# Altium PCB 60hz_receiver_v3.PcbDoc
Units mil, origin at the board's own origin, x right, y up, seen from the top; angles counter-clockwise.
Board outline 2650 x 1300 mil, 2 copper layers (Top Layer, Bottom Layer); 64 components, 31 nets, 144 pads, 25 vias.
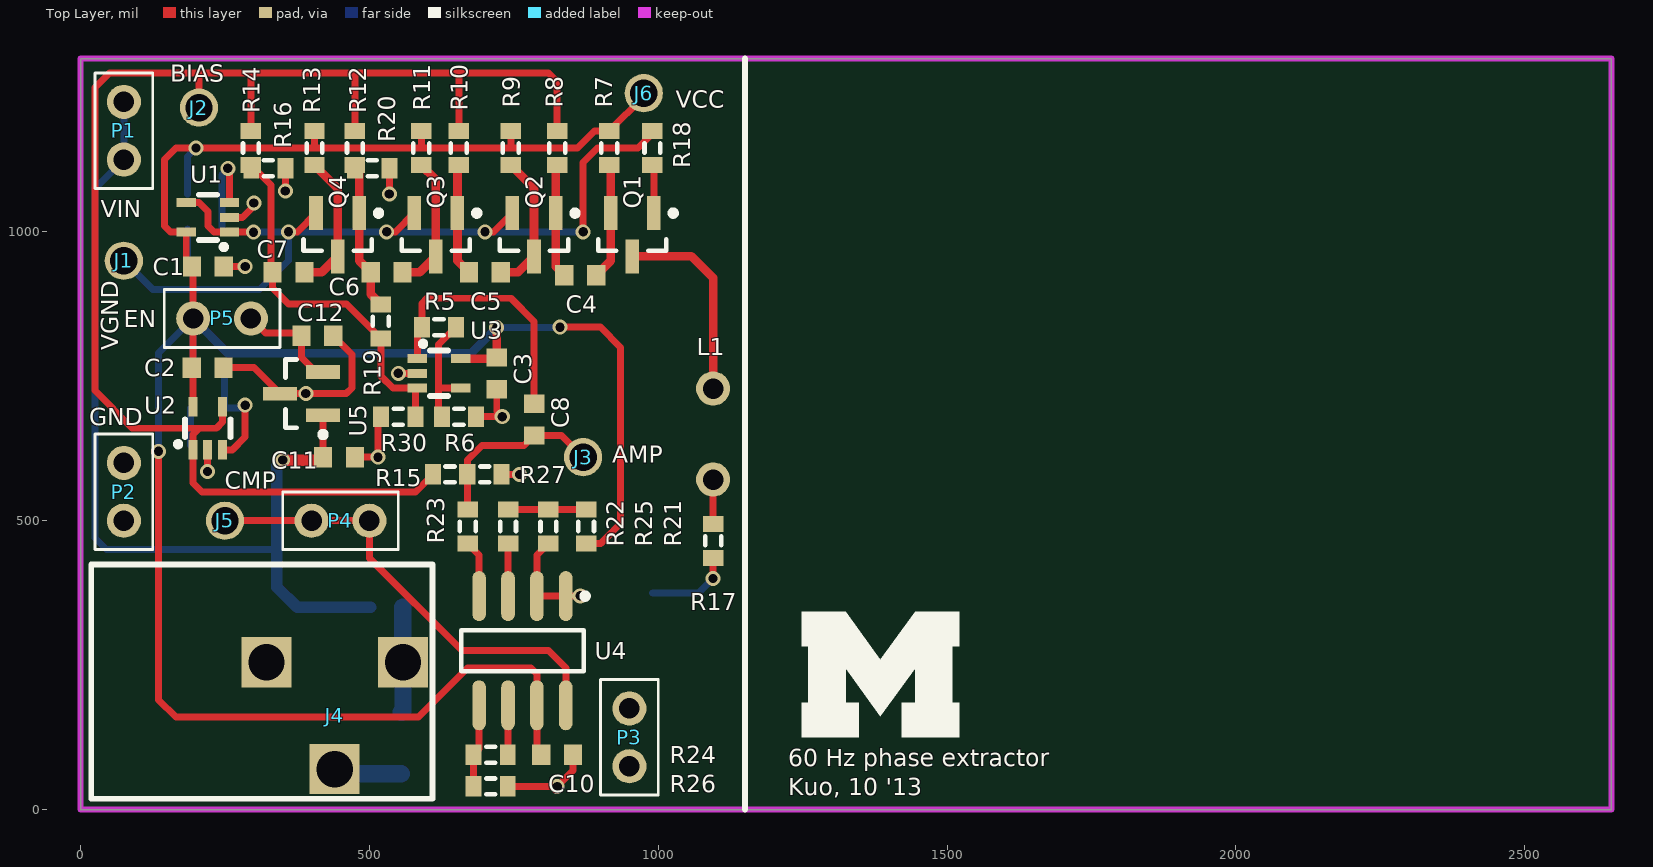
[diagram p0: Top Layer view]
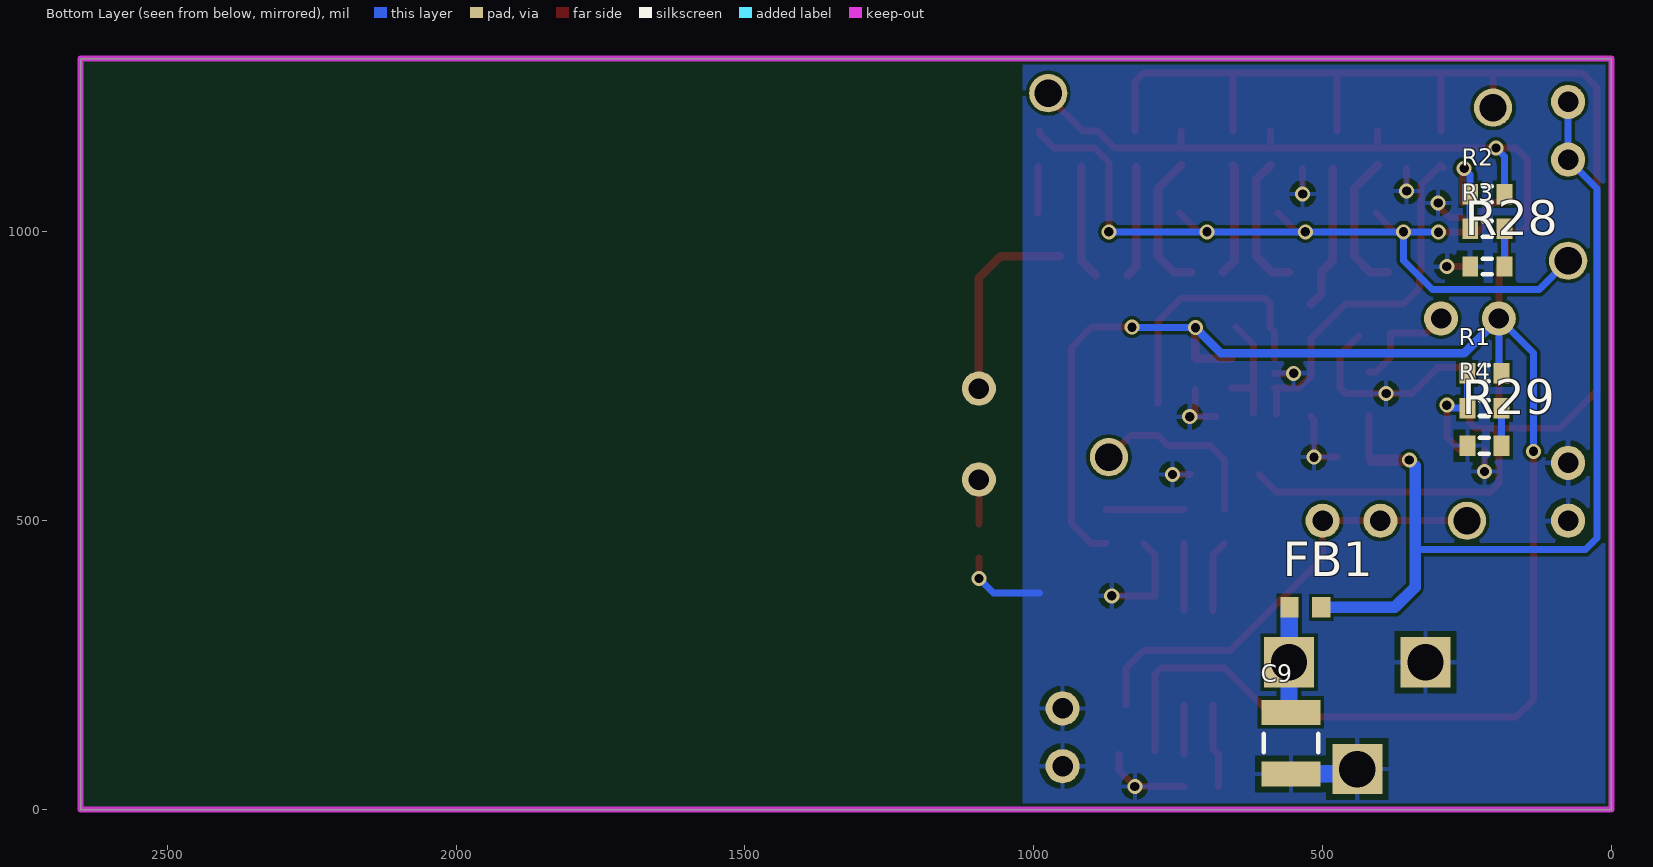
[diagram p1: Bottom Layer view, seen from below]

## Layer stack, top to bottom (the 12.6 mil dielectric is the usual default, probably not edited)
Top Layer: signal copper 1.4
Dielectric: dielectric 12.6, FR-4, Dk 4.8
Bottom Layer: signal copper 1.4

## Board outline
0,0 2650,0 2650,1300 0,1300

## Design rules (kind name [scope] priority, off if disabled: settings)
Clearance "Clearance~Sunstone Circuits" [All] p1: gap=6 // Sunstone Circuits Minimum Clearance Rule (MLB~4&6 Layer Designs)
HoleSize "HoleSize~Sunstone Circuits" [All] p1: absolutevalues=TRUE maxlimit=251 minlimit=8 maxpercent=80.000 minpercent=20.000 // Sunstone Circuits Hole Size Rule (MLB~4&6 Layer Designs)
HoleSize Testpoint [All] p2: absolutevalues=TRUE maxlimit=100 minlimit=1 maxpercent=80.000 minpercent=20.000
HoleSize TestPointUsage [All] p3: absolutevalues=TRUE maxlimit=100 minlimit=1 maxpercent=80.000 minpercent=20.000
MinimumAnnularRing "MinimumAnnularRing~Sunstone Circuits" [All] p1: minimumring=7 // Sunstone Circuits Minimum Annular Ring (MLB~4&6 Layer Designs)
PlaneClearance "PlaneClearance~Sunstone Circuits" [All] p1: clearance=12 // Sunstone Circuits Power Plane Clearance Rule (MLB~4&6 Layer Designs)
PlaneConnect "PlaneConnect~Sunstone Circuits" [All] p1: planeconnectstyle=Relief reliefexpansion=10 reliefentries=4 reliefconductorwidth=8 reliefairgap=10 // Sunstone Circuits Power Plane Connect Rule (MLB~4&6 Layer Designs)
PolygonConnect "PolygonConnect~Sunstone Circuits" [All] p1: connectstyle=Relief reliefconductorwidth=8 reliefentries=4 polygonreliefangle="90 Angle" airgapwidth=10 // Sunstone Circuits Polygon Connect Style (MLB~4&6 Layer Designs)
RoomDefinition 60hz_receiver_v3 [InComponentClass('60hz_receiver_v3')] p1: confinementstyle=ConfineIn formatcopy=TRUE lockcomponents=FALSE outline 1.35,3.78 1.35,439.29 12.5,439.29 12.5,1287.5 915.4,1287.5 915.4,1294.9 1035,1294.9 1035,1083.74 1045.71,1083.74 1045.71,771.27 1137.53,771.27 1137.53,528.73 1128.62,528.73 1128.62,405.79 1012.5,405.79 1012.5,12.5 769.21,12.5 769.21,6.38 624.29,6.38 624.29,3.78
RoutingVias "RoutingVias~Sunstone Circuits" [All] p1: holewidth=16 width=30 viastyle="Through Hole" minholewidth=8 minwidth=24 maxholewidth=20 maxwidth=40 // Sunstone Circuits Routing Vias Rule (MLB~4&6 Layer Designs)
ShortCircuit "ShortCircuit~Sunstone Circuits" [All] p1: allowed=FALSE // Sunstone Circuits Short Circuit Rule~Do Not Allow (MLB~4&6 Layer Designs)
SolderMaskExpansion "Tent vias" [isVia] p1: expansion=-10 // Tent vias
SolderMaskExpansion "SolderMaskExpansion~Sunstone Circuits" [All] p2: expansion=3 // Sunstone Circuits Solder Mask Expansion Rule (MLB~4&6 Layer Designs)
ViasUnderSMD "ViasUnderSMD~Sunstone Circuits" [All] p1: allowed=FALSE // Sunstone Circuits Vias Under SMD~Do Not Allow (MLB~4&6 Layer Designs)
Width "Width~Sunstone Circuits" [All] p1: maxlimit=100 minlimit=6 preferedwidth=10 // Sunstone Circuits Minimum Width Rule (MLB~4&6 Layer Designs)
24 further rules are at their usual default settings.

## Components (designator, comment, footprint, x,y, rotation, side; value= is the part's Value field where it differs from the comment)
C1 "Cap Semi" 1608[0603] 220.47,940 r180 top
C2 "Cap Semi" 1608[0603] 220,765 r180 top
C3 "Cap Semi" 1608[0603] 720.47,755 r90 top
C4 "Cap Semi" 1608[0603] 865,925 r180 top
C5 "Cap Semi" 1608[0603] 700,930 r180 top
C6 "Cap Semi" 1608[0603] 530,930 r180 top
C7 "Cap Semi" 1608[0603] 360,930 r180 top
C8 "Cap Semi" 1608[0603] 785,675 r270 top
C9 "47uF" C1210 555,115 r90 bottom
C10 "Cap Semi" 1608[0603] 825,95 r180 top
C11 "Cap Semi" 1608[0603] 447.4,610 r180 top
C12 "Cap Semi" 1608[0603] 410,820 r180 top
FB1 "BLM18PG300SN1D" 1608[0603] 530,350 r180 bottom
J1 "5004" TestPoint 75,950 r0 top
J2 "5004" TestPoint 205,1215 r0 top
J3 "5004" TestPoint 870,610 r0 top
J4 "PJ-102AH" PJ-102AH 440,255 r90 top
J5 "5004" TestPoint 250,500 r270 top
J6 "5004" TestPoint 975,1240 r0 top
L1 "Inductor Iron" "charging coil" 1095,650 r90 top
P1 "1 x 2 header" "1x2 header" 75,1175 r90 top
P2 "1 x 2 header" "1x2 header" 75,550 r90 top
P3 "1 x 2 header" "1x2 header" 950,125 r270 top
P4 "1 x 2 header" "1x2 header" 450,500 r180 top
P5 "1 x 2 header" "1x2 header" 245,850 r0 top
Q1 "2SK3557" SOT23-3N 955,995 r270 top
Q2 "Si2312CDS" SOT23-3N 785,995 r270 top
Q3 "Si2312CDS" SOT23-3N 615,995 r270 top
Q4 "Si2312CDS" SOT23-3N 445,995 r270 top
R1 "Res3" J1-0603 220,755 r0 bottom
R2 "Res3" J1-0603 215,1065 r180 bottom
R3 "Res3" J1-0603 215,1005 r0 bottom
R4 "Res3" J1-0603 220,695 r180 bottom
R5 "Res3" J1-0603 620.47,835 r0 top
R6 "Res3" J1-0603 655,680 r0 top
R7 "Res3" J1-0603 915,1145 r90 top
R8 "Res3" J1-0603 825,1145 r270 top
R9 "Res3" J1-0603 745,1145 r90 top
R10 "Res3" J1-0603 655,1145 r270 top
R11 "Res3" J1-0603 590,1145 r90 top
R12 "Res3" J1-0603 475,1145 r270 top
R13 "Res3" J1-0603 405,1145 r90 top
R14 "Res3" J1-0603 295,1145 r270 top
R15 "Res3" J1-0603 639.53,580 r0 top
R16 "Res3" J1-0603 325,1110 r0 top
R17 "Res3" J1-0603 1095,465 r270 top
R18 "Res3" J1-0603 990,1145 r270 top
R19 "Res3" J1-0603 520,845 r90 top
R20 "Res3" J1-0603 505,1110 r0 top
R21 "Res3" J1-0603 875,490 r270 top
R22 "Res3" J1-0603 740,490 r270 top
R23 "Res3" J1-0603 670,490 r270 top
R24 "Res3" J1-0603 710,95 r0 top
R25 "Res3" J1-0603 810,490 r90 top
R26 "Res3" J1-0603 710,40 r180 top
R27 "Res3" J1-0603 699.53,580 r0 top
R28 "Res3" J1-0603 215,940 r0 bottom
R29 "Res3" J1-0603 220,630 r0 bottom
R30 "Res3" J1-0603 550,680 r180 top
U1 "LPV521" SC70-5 220.47,1025 r90 top
U2 "LPV521" SC70-5 220,660 r0 top
U3 "LPV521" SC70-5 620.47,755 r270 top
U4 "LTC1540" SOIC-8 765,275 r270 top
U5 "MAX6010" SOT23-3N 382.4,720 r180 top

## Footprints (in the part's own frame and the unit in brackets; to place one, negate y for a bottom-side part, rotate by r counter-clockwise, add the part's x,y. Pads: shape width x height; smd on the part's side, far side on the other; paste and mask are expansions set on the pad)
"1x2 header" [mm] "1x2 header, 100 mils"
  round 1.5 hole 0.9: 1(-1.27,0) 2(1.27,0)
  silkscreen extent -2.54,-1.27 2.54,1.27, body extent -2.53,-1.26 2.53,1.26, height 8.38
1608[0603] [mm] "Chip Capacitor, Body 1.6x0.8mm, IPC High Density"
  rect 0.8x0.9 smd: 1(-0.7,0) 2(0.7,0)
  body extent -0.87,-0.48 0.87,0.48, height 1.3
C1210 [mm] "Chip Capacitor, Body 3.2x2.5mm, IPC High Density"
  rect 1.1x2.6 smd: 1(-1.35,0) 2(1.35,0)
  silkscreen extent -0.4,-1.2 0.4,1.2, body extent -1.7,-1.35 1.7,1.35, height 1.3
"charging coil" [mm]
  round 1.5 hole 0.9: 1(-2,0) 2(2,0)
J1-0603 [mm] "Chip Resistor, Body 1.6x0.8mm, IPC High Density"
  rect 0.7x0.9 smd: 1(-0.75,0) 2(0.75,0)
  silkscreen extent -0.2,-0.35 0.2,0.35, body extent -0.85,-0.48 0.85,0.48, height 0.9
PJ-102AH [mm] "Power Jack"
  rect 2.2x2.2 hole 1.6: 1(0,-3) 2(0,3) 3(-4.7,0)
  silkscreen extent -6,-4.3 4.3,10.7, body extent -5.75,-3.99 4.08,10.89, height 10
SC70-5 [mm]
  rect 0.4x0.85 smd: 1(-0.65,-0.95) 2(0,-0.95) 3(0.65,-0.95) 4(0.65,0.95) 5(-0.65,0.95)
  silkscreen extent -1.4,-0.8 1,0.4, body extent -0.9,-0.6 0.9,0.6, height 0.8
SOIC-8 [mm] "SOIC, 8-Leads, Body 5.10x3.91mm, Pitch 1.27mm, IPC Medium Density"
  oval 2.2x0.6 smd: 1(-2.4,1.905) 2(-2.4,0.635) 3(-2.4,-0.635) 4(-2.4,-1.905) 5(2.4,-1.905) 6(2.4,-0.635) 7(2.4,0.635) 8(2.4,1.905)
  silkscreen extent -2.52,-2.7 0.9,2.88, body extent -2,-2.7 2,2.7, height 1.75
SOT23-3N [mm] "SOT23, 3-Leads, Body 2.9x1.3mm, Pitch 0.95mm, Lead Span 2.5mm, IPC Medium Density"
  rect 1.5x0.6 smd: 1(-0.95,0.95) 2(-0.95,-0.95) 3(0.95,0)
  silkscreen extent -1.07,-1.5 0.7,1.93, body extent -0.7,-1.5 0.7,1.5, height 1.1
TestPoint [mm]
  round 1.68 hole 1.2: 1(0,0)
  body extent -1.26,-1.27 1.27,1.27, height 4.57

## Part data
C1 C2 C3 C4 C5 C6 C7 C8 C10 C11 C12: "Capacitor (Semiconductor SIM Model)"
C9: library part "Cap Semi", "Capacitor (Semiconductor SIM Model)"
FB1: library part "Ferrite Bead", "FERRITE CHIP 30 OHM 1000MA 0603"
J1 J2 J3 J5 J6: library part TestPoint, "TEST POINT PC MINI .040\"D YELLOW"
J4: "CONN PWR JACK 2.1X5.5MM HIGH CUR"
L1: "Magnetic-Core Inductor"
P1 P2 P3 P4 P5: "100 mils standard header"
Q1: "N-Channel JFET"
Q2 Q3 Q4: "N-Channel 20 V (D-S) MOSFET"
R1 R2 R3 R4 R5 R6 R7 R8 R9 R10 R11 R12 R13 R14 R15 R16 R17 R18 R19 R20 R21 R22 R23 R24 R25 R26 R27 R28 R29 R30: "Resistor"
U1 U2 U3: "Nanopower, 1.8V, RRIO, CMOS Input, Operational Amplifier"
U4: "Nanopower Comparator  with Reference"
U5: "Precision Micropower Shunt Voltage Reference"

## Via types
v1: diameter 26, hole 16, Top Layer to Bottom Layer, 25 vias

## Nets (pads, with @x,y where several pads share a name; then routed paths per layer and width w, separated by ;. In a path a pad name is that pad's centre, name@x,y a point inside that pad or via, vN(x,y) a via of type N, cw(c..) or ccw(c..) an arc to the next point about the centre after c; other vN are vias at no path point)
AMP_OUT: C8.1 R5.1 U3.1 | length 455.4
  Top Layer w12: U3.1 583.07,827.13 R5.1 590.94,875.94 600,885 745,885 785,845 C8.1
AMP_OUT_OFFSET: C8.2 J3.1 R15.2 R23.1 R27.1 | length 318.6
  Top Layer w12: R23.1 670,605 695,630 767.56,630 C8.2 832.56,647.44 J3.1
CMP_REF: R21.1 R22.1 R25.2 | length 135
  Top Layer w12: R22.1 R21.1
GND: C1.1 C2.1 C3.1 C9.1 C10.1 C11.1 C12.1 J4.2 J4.3 P2.1 P2.2 P3.1 P3.2 R6.2 R16.2 R17.2 R20.2 R25.1 R26.1 R27.2 R28.2 R29.2 R30.2 U1.2 U2.2 U3.2 U4.1 U4.2 U5.3 | length 1431.7
  Top Layer w12: v1(220,585) U2.2 ; C2.1 300,765 U5.3 v1(390,720) 460,720 470,730 470,787.56 C12.1 ; C1.1 v1(285,940) ; U1.2 280,1025 300,1045 v1(300,1050) ; v1(354.53,1070.47) R16.2 ; C11.1 v1(515,610) 515,674.53 R30.2 ; v1(534.53,1065.47) R20.2 ; v1@549.82,755.18 v1(550.18,755.18) 550.36,755 U3.2 ; R6.2 v1(730,680) 720.47,689.53 C3.1 ; R27.2 v1(760,580) ; R26.1 v1(825,40) 852.56,67.56 C10.1 ; R25.1 790,440.47 U4.2 U4.1 840.51,370 v1(865,370) ; v1(1095,400) R17.2
  Bottom Layer w12: 990,375 1070,375 v1(1095,400)
  Bottom Layer w30: J4.3 448.11,61.85 C9.1
NetC4_1: C4.1 Q1.2 R7.1 | length 198.2
  Top Layer w15: C4.1 917.6,950.04 Q1.2 R7.1@917.6,1112.87
NetC4_2: C4.2 Q2.1 R8.2 | length 194.1
  Top Layer w15: R8.2@822.4,1112.87 Q2.1 822.4,940.04 C4.2
NetC5_1: C5.1 Q2.3 R9.1 | length 243.3
  Top Layer w15: C5.1 757.4,930 Q2.3 785,1075.47 R9.1
NetC5_2: C5.2 Q3.1 R10.2 | length 194.8
  Top Layer w15: R10.2 652.4,1112.87 Q3.1 652.4,950.04 C5.2
NetC6_1: C6.1 Q3.3 R11.1 | length 237.1
  Top Layer w15: C6.1 587.4,930 Q3.3 615,1090.47 R11.1
NetC6_2: C6.2 Q4.1 R12.2 R19.2 R20.1 | length 249.1
  Top Layer w15: R20.1@482.4,1108.07 Q4.1 482.4,950.04 C6.2 502.44,892.09 R19.2
NetC7_1: C7.1 Q4.3 R13.1 | length 243.3
  Top Layer w15: C7.1 417.4,930 Q4.3 445,1075.47 R13.1
NetC7_2: C7.2 R14.2 R16.1 R19.1 R30.1 U3.3 | length 637.3
  Top Layer w12: R14.2@290.47,1110.94 R14.2 329.53,1080.94 329.53,932.91 C7.2 332.44,902.56 360,875 460.47,875 R19.1 520,750 540.59,729.41 U3.3 ; R30.1@580,684.53 U3.3@580,726.34
NetC9_2: C9.2 FB1.1 J4.1 | length 182.6
  Bottom Layer w30: C9.2 558.11,171.26 J4.1 ; J4.1@557.56,255.55 FB1.1
NetC12_2: C12.2 P5.2 U5.2 | length 188
  Top Layer w12: P5.2 320,825 382.44,825 382.44,782.56 407.6,757.4 U5.2
NetJ5_1: J5.1 P4.1 P4.2 U4.8 | length 798.2
  Top Layer w12: J5.1 P4.2 P4.1 500,435 660,275 810,275 840,245 U4.8
NetL1_1: L1.1 R17.1 | length 76.7
  Top Layer w12: R17.1 L1.1
NetL1_2: L1.2 Q1.3 | length 346.8
  Top Layer w15: Q1.3 1057.4,957.6 1095,920 L1.2
NetQ1_1: Q1.1 R18.2 | length 80.7
  Top Layer w12: Q1.1 R18.2@992.4,1113.07
NetR3_1: R3.1 R28.1 | length 65
  Bottom Layer w12: R28.1 R3.1
NetR4_2: R4.2 R29.1 | length 65
  Bottom Layer w12: R29.1 R4.2
NetR5_2: R5.2 R6.1 U3.4 | length 199.2
  Top Layer w12: R6.1@620,685.47 620,805 R5.2 ; 620.59,729.41 U3.4
NetR22_2: R22.2 U4.3 | length 116
  Top Layer w12: U4.3@740,344.49 R22.2
NetR23_2: R23.2 U4.4 | length 124.3
  Top Layer w12: R23.2 690,440.47 U4.4 U4.4@690,344.49
NetR24_1: R24.1 R26.2 U4.5 | length 144.5
  Top Layer w12: R26.2 R24.1 690,104.53 U4.5
NetR24_2: R24.2 U4.6 | length 85
  Top Layer w12: R24.2@740,95.47 U4.6
REF_GND: R2.1 R3.2 U1.3 | length 155.8
  Top Layer w12: v1(255,1110) 257.87,1107.13 U1.3
  Bottom Layer w12: R3.2 R2.1 244.53,1099.53 ; v1@254.53,1109.53 v1(255,1110)
VBIAS: R1.2 R4.1 U2.3 | length 196.2
  Top Layer w12: U2.3 262.6,622.6 285,645 v1(285,700)
  Bottom Layer w12: R4.1 280,695 v1(285,700) ; R4.1@249.53,700 R1.2
VBIAS_BUFFERED: J2.1 R8.1 R10.1 R12.1 R14.1 R15.1 U2.1 U2.4 | length 2599.6
  Top Layer w12: 89.41,660.59 25,725 25,1250 50,1275 205,1275 ; 90,660 205,660 ; J2.1 205,1275 ; U2.4 245.59,670.59 235,660 205,660 ; R14.1 295,1275 ; R12.1 475,1275 ; R15.1 580,550 210,550 194.41,565.59 U2.1 194.41,649.41 205,660 ; R10.1 655,1275 ; R8.1 825,1260 810,1275 475,1275 ; 205,1275 295,1275 ; 295,1275 475,1275
VCC3: C1.2 C2.2 C3.2 C10.2 J6.1 P5.1 R1.1 R2.2 R7.2 R9.2 R11.2 R13.2 R21.2 U1.5 U2.5 U3.5 U4.7 | length 4416.5
  Top Layer w12: v1(135,620) 135,190 165,160 585,160 670,245 780,245 790,235 U4.7 C10.2@790,102.44 ; C1.2 183.07,949.84 U1.5 155.59,999.41 145,1010 145,1125 165,1145 v1(200,1145) 860,1145 889.53,1174.53 R7.2 975,1234.53 J6.1@975,1235 ; U2.5@195,697.99 P5.1 C1.2@195,937.91 ; 405,1145 R13.2 ; 590,1145 R11.2 ; 745,1145 R9.2 ; v1(830,835) 900,835 935,800 935,495 900.47,460.47 R21.2
  Top Layer w15: U3.5 C3.2@718.5,780.59 ; v1(720,834.06) 720.47,834.53 C3.2
  Bottom Layer w12: v1(135,620) 135,790 P5.1 R1.1@195,759.53 ; R2.2 185.47,1130.47 v1(200,1145) ; v1(720,834.06) 829.06,834.06 v1(830,835)
  Bottom Layer w15: P5.1 255,790 675.94,790 v1(720,834.06)
VGND: J1.1 Q2.2 Q3.2 Q4.2 R18.1 U1.1 U1.4 | length 1546.9
  Top Layer w12: U1.4 204.88,1050.59 220.47,1035 220.47,1010 231.06,999.41 U1.1 v1(299.41,999.41) ; v1(360,1000) 375.2,1000 Q4.2 ; v1(530,1000) 545.2,1000 Q3.2 ; v1(700,1000) 715.2,1000 Q2.2 ; v1(870,1000) 870,1120 895,1145 965,1145 990,1170 R18.1
  Bottom Layer w12: J1.1 125,900 310,900 360,950 v1(360,1000) v1(530,1000) v1(700,1000) v1(870,1000) ; v1(299.41,999.41) v1@359.41,999.41
VIN: C11.2 FB1.2 P1.1 P1.2 U5.1 | length 1637.5
  Top Layer w12: C11.2 U5.1
  Top Layer w20: v1(350,605) C11.2@414.84,605
  Bottom Layer w12: P1.2 P1.1 25,1075 25,470 45,450 340,450
  Bottom Layer w20: v1(350,605) 340,595 340,450 340,385 375,350 FB1.2

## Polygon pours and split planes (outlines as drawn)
GND on Bottom Layer "Bottom Layer-No Net" (solid, pour order 2): 1018.78,1288.78 -6.22,1288.78 -6.22,-11.22 1018.78,-11.22

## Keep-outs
Keep-Out Layer:
  the board outline again, w10

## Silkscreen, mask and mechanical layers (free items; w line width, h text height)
Top Overlay:
  region: 1248.28,124.75 1347.37,124.75 1347.37,185 1324.27,185 1324.27,244.58 1384.52,161.57 1444.77,244.58 1444.77,185 1421.68,185 1421.68,124.75 1520.76,124.75 1520.76,185 1509.04,185 1509.04,282.41 1520.76,282.41 1520.76,341.99 1444.44,341.99 1384.52,259.65 1324.6,341.99 1248.28,341.99 1248.28,282.41 1260,282.41 1260,185 1248.28,185
  lines w10: 1150,0 1150,1300
  text "BIAS" at 155,1260 h30
  text "VCC" at 1030,1215 h30
  text "VIN" at 35,1025 h30
  text "EN" at 75,835 h30
  text "VGND" at 65,795 h30 r90
  text "GND" at 15,665 h30
  text "AMP" at 920,600 h30
  text "CMP" at 250,555 h30
  text "60 Hz phase extractor" at 1225,75 h30
  text "Kuo, 10 '13" at 1225,25 h30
